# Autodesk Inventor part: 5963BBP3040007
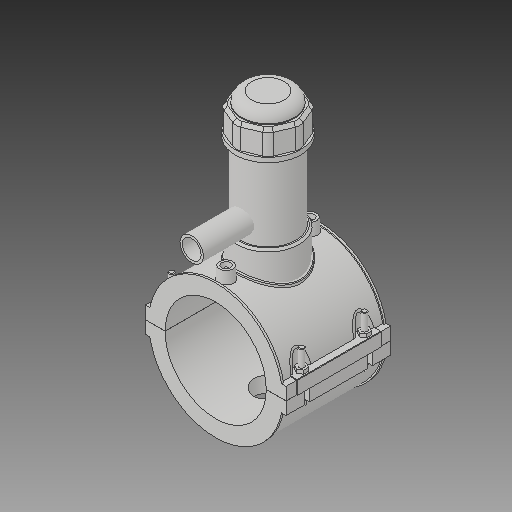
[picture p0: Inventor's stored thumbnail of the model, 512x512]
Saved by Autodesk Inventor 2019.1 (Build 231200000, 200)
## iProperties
Created: 2017-07
Part Number: 5963BBP3040007
Material: Generic
Description: PLASSON TAPPING SADDLE 4''IPS x 3/4''IPS
Document SubType Name: Modeling
Designer: KIM
Density: 1 g/cm^3
Appearance: Default
Author: KIM
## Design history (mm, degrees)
derived "5963BBP_5963BUP.ipt"
feature "Solid1::5963BBP_5963BUP.ipt"
feature "Solid2::5963BBP_5963BUP.ipt"
feature "Solid3::5963BBP_5963BUP.ipt"
tag "TaggingFeature1"
body "Solid1"
body "Solid2"
body "Solid3"
other parameters: "d0" = 114.1, "d2" = 159.004, "d3" = 28.525, "d4" = 118.11, "d5" = 0, "d6" = 0.1, "d8" = 0, "d19" = 6, "d20" = 6, "d21" = 70.866, "d23" = 0, "d24" = 35.433, "d26" = 0, "d27" = 3, "d28" = 3, "d29" = 3, "d30" = 38.03333, "d31" = 6, "d32" = 0, "d33" = 0, "d34" = 0.6, "d40" = 77.1316, "d41" = 74.165, "d43" = 0, "d45" = 0, "d47" = 145.031, "d70" = 15, "d72" = 0, "d73" = 6, "d75" = 5, "d76" = 0, "d77" = 5.705, "d78" = 87.05, "d79" = 15, "d80" = 47.244, "d82" = 5 deg, "d84" = 4, "d85" = 14, "d86" = 0, "d87" = 3, "d88" = 0, "d89" = 1, "d90" = 1, "d91" = 94.488, "d92" = 0, "d93" = 0.5, "d94" = 60.05263, "d96" = 151.2966, "d97" = 2.3622, "d98" = 0, "d102" = 1.141, "d120" = 140 deg, "d121" = 24.228, "d122" = 20 deg, "d123" = 296.66, "d124" = 88.998, "d126" = 0, "d143" = 117.523, "d145" = 26.33077, "d149" = 1.7115, "d150" = 28.96385, "d153" = 118.11, "d154" = 0, "d156" = 74.165, "d157" = 160 deg, "d159" = 6.846, "d161" = 1.7115, "d162" = 70.866, "d163" = 0, "d164" = 57.05, "d167" = 11.41, "d168" = 72.3561, "d170" = 3.2805, "d172" = 0, "d173" = 1, "d175" = 57.05, "d176" = 20 deg, "d177" = 7.987, "d178" = 34.23, "d180" = 0, "d183" = 13.692, "d184" = 6.3896, "d185" = 38.38575, "d186" = 38.38575, "d187" = 74.165, "d188" = 10.269, "d189" = 7.987, "d190" = 0, "d191" = 111.2475, "d193" = 6.9984, "d194" = 4.13385, "d195" = 90 deg, "d197" = 0, "d199" = 0, "d200" = 17.115, "d202" = 0, "d203" = 177.038, "d204" = 70.45675, "d205" = 51.9155, "d206" = 63.04025, "d207" = 132.7785, "d208" = 138.08964, "d209" = 164.64534, "d210" = 63.7819, "d211" = 74.165, "d212" = 59.332, "d213" = 46.5516, "d216" = 0, "d217" = 11.41, "d218" = 11.41, "d219" = 2.282, "d222" = 114.1, "d224" = 0, "d225" = 65.024, "d226" = 26.6, "d227" = 21.28, "d228" = 86.106, "d230" = 3.423, "d_" = 114.1, "B_" = 159.004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
